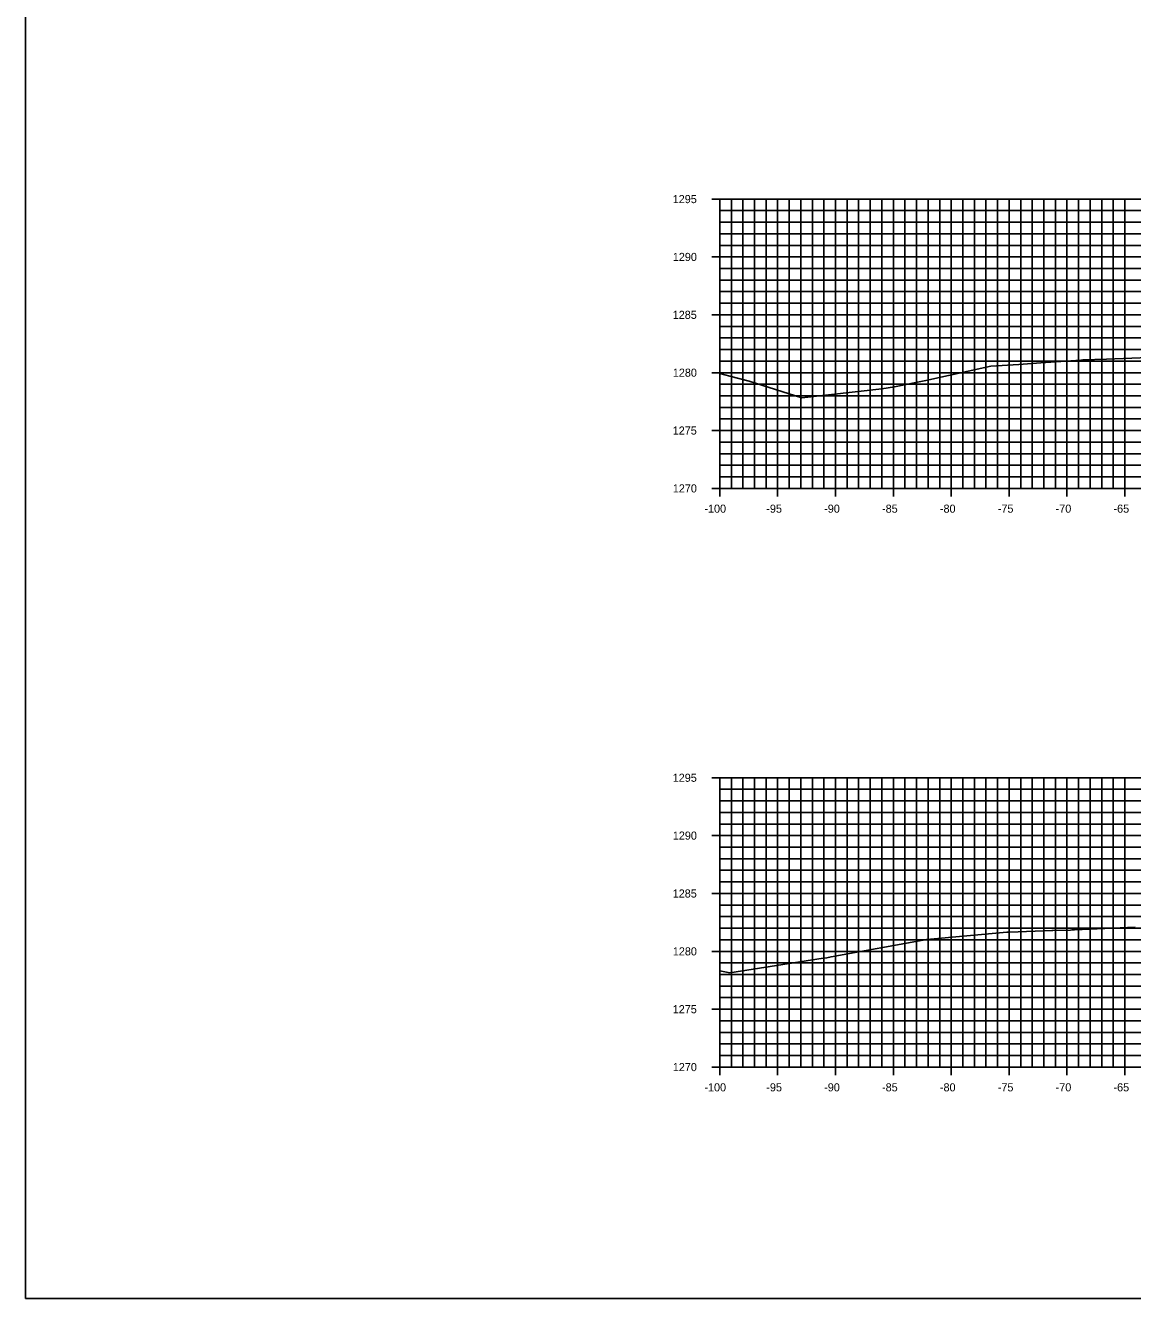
# Model space of a CAD drawing. Extents: x 674939 to 678919, y 750652 to 765176.
# Drawn here: x 678578.5 to 678674.2, y 758972.6 to 759082.6 of the extents above; entities that cross this region are included whole.
import ezdxf

# ---------------------------------------------------------------- set-up
doc = ezdxf.new("R2010")
doc.units = 0
for name, color, linetype in [('Level 10', 7, 'Continuous'), ('Level 20', 7, 'Continuous'), ('Level 4', 7, 'Continuous'), ('Level 8', 7, 'Continuous'), ('Level 9', 7, 'Continuous')]:
    doc.layers.add(name, color=color, linetype=linetype)

msp = doc.modelspace()

# ---------------------------------------------------------------- linework, layer by layer
at = {"layer": 'Level 10'}
for points in [[(678638.53, 759052.49), (678639.41, 759052.24), (678641.08, 759051.82), (678645.63, 759050.37), (678652.53, 759051.16), (678653.62, 759051.32), (678656.33, 759051.86), (678661.96, 759053.1), (678664.37, 759053.27), (678666.28, 759053.41), (678669.72, 759053.64), (678669.9, 759053.66), (678671.95, 759053.73), (678676.31, 759053.88)], [(678638.53, 759000.86), (678639.41, 759000.69), (678647.47, 759001.97), (678647.77, 759002), (678648.14, 759002.09), (678656.42, 759003.58), (678663.32, 759004.2), (678663.44, 759004.21), (678663.59, 759004.22), (678667.23, 759004.36), (678667.3, 759004.36), (678667.31, 759004.36), (678668.84, 759004.39), (678668.94, 759004.4), (678669.17, 759004.41), (678674.42, 759004.64)]]:
    msp.add_lwpolyline(points, dxfattribs=at)
at = {"layer": 'Level 20'}
for p, q in [((678638.53, 759067.55), (678838.53, 759067.55)), ((678638.53, 759042.55), (678638.53, 759067.55)), ((678639.53, 759042.55), (678639.53, 759067.55)), ((678640.53, 759042.55), (678640.53, 759067.55)), ((678641.53, 759042.55), (678641.53, 759067.55)), ((678642.53, 759042.55), (678642.53, 759067.55)), ((678643.53, 759042.55), (678643.53, 759067.55)), ((678644.53, 759042.55), (678644.53, 759067.55)), ((678645.53, 759042.55), (678645.53, 759067.55)), ((678646.53, 759042.55), (678646.53, 759067.55)), ((678647.53, 759042.55), (678647.53, 759067.55)), ((678648.53, 759042.55), (678648.53, 759067.55)), ((678649.53, 759042.55), (678649.53, 759067.55)), ((678650.53, 759042.55), (678650.53, 759067.55)), ((678651.53, 759042.55), (678651.53, 759067.55)), ((678652.53, 759042.55), (678652.53, 759067.55)), ((678653.53, 759042.55), (678653.53, 759067.55)), ((678654.53, 759042.55), (678654.53, 759067.55)), ((678655.53, 759042.55), (678655.53, 759067.55)), ((678656.53, 759042.55), (678656.53, 759067.55)), ((678657.53, 759042.55), (678657.53, 759067.55)), ((678658.53, 759042.55), (678658.53, 759067.55)), ((678659.53, 759042.55), (678659.53, 759067.55)), ((678660.53, 759042.55), (678660.53, 759067.55)), ((678661.53, 759042.55), (678661.53, 759067.55)), ((678662.53, 759042.55), (678662.53, 759067.55)), ((678663.53, 759042.55), (678663.53, 759067.55)), ((678664.53, 759042.55), (678664.53, 759067.55)), ((678665.53, 759042.55), (678665.53, 759067.55)), ((678666.53, 759042.55), (678666.53, 759067.55)), ((678667.53, 759042.55), (678667.53, 759067.55)), ((678668.53, 759042.55), (678668.53, 759067.55)), ((678669.53, 759042.55), (678669.53, 759067.55)), ((678670.53, 759042.55), (678670.53, 759067.55)), ((678671.53, 759042.55), (678671.53, 759067.55)), ((678672.53, 759042.55), (678672.53, 759067.55)), ((678673.53, 759042.55), (678673.53, 759067.55)), ((678638.53, 759066.55), (678838.53, 759066.55)), ((678638.53, 759065.55), (678838.53, 759065.55)), ((678638.53, 759064.55), (678838.53, 759064.55)), ((678638.53, 759063.55), (678838.53, 759063.55)), ((678638.53, 759062.55), (678838.53, 759062.55)), ((678638.53, 759061.55), (678838.53, 759061.55)), ((678638.53, 759060.55), (678838.53, 759060.55)), ((678638.53, 759059.55), (678838.53, 759059.55)), ((678638.53, 759058.55), (678838.53, 759058.55)), ((678638.53, 759057.55), (678838.53, 759057.55)), ((678638.53, 759056.55), (678838.53, 759056.55)), ((678638.53, 759055.55), (678838.53, 759055.55)), ((678638.53, 759054.55), (678838.53, 759054.55)), ((678638.53, 759053.55), (678838.53, 759053.55)), ((678638.53, 759052.55), (678838.53, 759052.55)), ((678638.53, 759051.55), (678838.53, 759051.55)), ((678638.53, 759050.55), (678838.53, 759050.55)), ((678638.53, 759049.55), (678838.53, 759049.55)), ((678638.53, 759048.55), (678838.53, 759048.55)), ((678638.53, 759047.55), (678838.53, 759047.55)), ((678638.53, 759046.55), (678838.53, 759046.55)), ((678638.53, 759045.55), (678838.53, 759045.55)), ((678638.53, 759044.55), (678838.53, 759044.55)), ((678638.53, 759043.55), (678838.53, 759043.55)), ((678638.53, 759042.55), (678838.53, 759042.55)), ((678638.53, 759017.55), (678838.53, 759017.55)), ((678638.53, 758992.55), (678638.53, 759017.55)), ((678638.53, 759016.55), (678838.53, 759016.55)), ((678639.53, 758992.55), (678639.53, 759017.55)), ((678640.53, 758992.55), (678640.53, 759017.55)), ((678641.53, 758992.55), (678641.53, 759017.55)), ((678642.53, 758992.55), (678642.53, 759017.55)), ((678643.53, 758992.55), (678643.53, 759017.55)), ((678644.53, 758992.55), (678644.53, 759017.55)), ((678645.53, 758992.55), (678645.53, 759017.55)), ((678646.53, 758992.55), (678646.53, 759017.55)), ((678647.53, 758992.55), (678647.53, 759017.55)), ((678648.53, 758992.55), (678648.53, 759017.55)), ((678649.53, 758992.55), (678649.53, 759017.55)), ((678650.53, 758992.55), (678650.53, 759017.55)), ((678651.53, 758992.55), (678651.53, 759017.55)), ((678652.53, 758992.55), (678652.53, 759017.55)), ((678653.53, 758992.55), (678653.53, 759017.55)), ((678654.53, 758992.55), (678654.53, 759017.55)), ((678655.53, 758992.55), (678655.53, 759017.55)), ((678656.53, 758992.55), (678656.53, 759017.55)), ((678657.53, 758992.55), (678657.53, 759017.55)), ((678658.53, 758992.55), (678658.53, 759017.55)), ((678659.53, 758992.55), (678659.53, 759017.55)), ((678660.53, 758992.55), (678660.53, 759017.55)), ((678661.53, 758992.55), (678661.53, 759017.55)), ((678662.53, 758992.55), (678662.53, 759017.55)), ((678663.53, 758992.55), (678663.53, 759017.55)), ((678664.53, 758992.55), (678664.53, 759017.55)), ((678665.53, 758992.55), (678665.53, 759017.55)), ((678666.53, 758992.55), (678666.53, 759017.55)), ((678667.53, 758992.55), (678667.53, 759017.55)), ((678668.53, 758992.55), (678668.53, 759017.55)), ((678669.53, 758992.55), (678669.53, 759017.55)), ((678670.53, 758992.55), (678670.53, 759017.55)), ((678671.53, 758992.55), (678671.53, 759017.55)), ((678672.53, 758992.55), (678672.53, 759017.55)), ((678673.53, 758992.55), (678673.53, 759017.55)), ((678638.53, 759015.55), (678838.53, 759015.55)), ((678638.53, 759014.55), (678838.53, 759014.55)), ((678638.53, 759013.55), (678838.53, 759013.55)), ((678638.53, 759012.55), (678838.53, 759012.55)), ((678638.53, 759011.55), (678838.53, 759011.55)), ((678638.53, 759010.55), (678838.53, 759010.55)), ((678638.53, 759009.55), (678838.53, 759009.55)), ((678638.53, 759008.55), (678838.53, 759008.55)), ((678638.53, 759007.55), (678838.53, 759007.55)), ((678638.53, 759006.55), (678838.53, 759006.55)), ((678638.53, 759005.55), (678838.53, 759005.55)), ((678638.53, 759004.55), (678838.53, 759004.55)), ((678638.53, 759003.55), (678838.53, 759003.55)), ((678638.53, 759002.55), (678838.53, 759002.55)), ((678638.53, 759001.55), (678838.53, 759001.55)), ((678638.53, 759000.55), (678838.53, 759000.55)), ((678638.53, 758999.55), (678838.53, 758999.55)), ((678638.53, 758998.55), (678838.53, 758998.55)), ((678638.53, 758997.55), (678838.53, 758997.55)), ((678638.53, 758996.55), (678838.53, 758996.55)), ((678638.53, 758995.55), (678838.53, 758995.55)), ((678638.53, 758994.55), (678838.53, 758994.55)), ((678638.53, 758993.55), (678838.53, 758993.55)), ((678638.53, 758992.55), (678838.53, 758992.55))]:
    msp.add_line(p, q, dxfattribs=at)
at = {"layer": 'Level 4'}
msp.add_lwpolyline([(678578.53, 758972.55), (678918.53, 758972.55), (678918.53, 759192.55), (678578.53, 759192.55)], close=True, dxfattribs=at)
at = {"layer": 'Level 8'}
for p, q in [((678637.83, 759067.55), (678639.23, 759067.55)), ((678638.53, 759042.55), (678638.53, 759067.55)), ((678638.53, 759066.55), (678638.88, 759066.55)), ((678638.53, 759065.55), (678638.88, 759065.55)), ((678638.53, 759064.55), (678638.88, 759064.55)), ((678638.53, 759063.55), (678638.88, 759063.55)), ((678637.83, 759062.55), (678639.23, 759062.55)), ((678638.53, 759061.55), (678638.88, 759061.55)), ((678638.53, 759060.55), (678638.88, 759060.55)), ((678638.53, 759059.55), (678638.88, 759059.55)), ((678638.53, 759058.55), (678638.88, 759058.55)), ((678637.83, 759057.55), (678639.23, 759057.55)), ((678638.53, 759056.55), (678638.88, 759056.55)), ((678638.53, 759055.55), (678638.88, 759055.55)), ((678638.53, 759054.55), (678638.88, 759054.55)), ((678638.53, 759053.55), (678638.88, 759053.55)), ((678637.83, 759052.55), (678639.23, 759052.55)), ((678638.53, 759051.55), (678638.88, 759051.55)), ((678638.53, 759050.55), (678638.88, 759050.55)), ((678638.53, 759049.55), (678638.88, 759049.55)), ((678638.53, 759048.55), (678638.88, 759048.55)), ((678637.83, 759047.55), (678639.23, 759047.55)), ((678638.53, 759046.55), (678638.88, 759046.55)), ((678638.53, 759045.55), (678638.88, 759045.55)), ((678638.53, 759044.55), (678638.88, 759044.55)), ((678638.53, 759043.55), (678638.88, 759043.55)), ((678638.53, 759041.85), (678638.53, 759043.25)), ((678643.53, 759041.85), (678643.53, 759043.25)), ((678648.53, 759041.85), (678648.53, 759043.25)), ((678653.53, 759041.85), (678653.53, 759043.25)), ((678658.53, 759041.85), (678658.53, 759043.25)), ((678663.53, 759041.85), (678663.53, 759043.25)), ((678668.53, 759041.85), (678668.53, 759043.25)), ((678673.53, 759041.85), (678673.53, 759043.25)), ((678637.83, 759042.55), (678639.23, 759042.55)), ((678638.53, 759042.55), (678838.53, 759042.55)), ((678637.83, 759017.55), (678639.23, 759017.55)), ((678638.53, 758992.55), (678638.53, 759017.55)), ((678638.53, 759016.55), (678638.88, 759016.55)), ((678638.53, 759015.55), (678638.88, 759015.55)), ((678638.53, 759014.55), (678638.88, 759014.55)), ((678638.53, 759013.55), (678638.88, 759013.55)), ((678637.83, 759012.55), (678639.23, 759012.55)), ((678638.53, 759011.55), (678638.88, 759011.55)), ((678638.53, 759010.55), (678638.88, 759010.55)), ((678638.53, 759009.55), (678638.88, 759009.55)), ((678638.53, 759008.55), (678638.88, 759008.55)), ((678637.83, 759007.55), (678639.23, 759007.55)), ((678638.53, 759006.55), (678638.88, 759006.55)), ((678638.53, 759005.55), (678638.88, 759005.55)), ((678638.53, 759004.55), (678638.88, 759004.55)), ((678638.53, 759003.55), (678638.88, 759003.55)), ((678637.83, 759002.55), (678639.23, 759002.55)), ((678638.53, 759001.55), (678638.88, 759001.55)), ((678638.53, 759000.55), (678638.88, 759000.55)), ((678638.53, 758999.55), (678638.88, 758999.55)), ((678638.53, 758998.55), (678638.88, 758998.55)), ((678637.83, 758997.55), (678639.23, 758997.55)), ((678638.53, 758996.55), (678638.88, 758996.55)), ((678638.53, 758995.55), (678638.88, 758995.55)), ((678638.53, 758994.55), (678638.88, 758994.55)), ((678638.53, 758993.55), (678638.88, 758993.55)), ((678637.83, 758992.55), (678639.23, 758992.55)), ((678638.53, 758991.85), (678638.53, 758993.25)), ((678638.53, 758992.55), (678838.53, 758992.55)), ((678643.53, 758991.85), (678643.53, 758993.25)), ((678648.53, 758991.85), (678648.53, 758993.25)), ((678653.53, 758991.85), (678653.53, 758993.25)), ((678658.53, 758991.85), (678658.53, 758993.25)), ((678663.53, 758991.85), (678663.53, 758993.25)), ((678668.53, 758991.85), (678668.53, 758993.25)), ((678673.53, 758991.85), (678673.53, 758993.25))]:
    msp.add_line(p, q, dxfattribs=at)

# ---------------------------------------------------------------- texts
at = {"layer": 'Level 9'}
for s, p in [('1295', (678634.46, 759067.2)), ('1290', (678634.47, 759062.2)), ('1285', (678634.46, 759057.2)), ('1280', (678634.47, 759052.2)), ('1275', (678634.46, 759047.2)), ('1270', (678634.47, 759042.2)), ('-100', (678637.2, 759040.45)), ('-95', (678642.55, 759040.45)), ('-90', (678647.55, 759040.45)), ('-85', (678652.55, 759040.45)), ('-80', (678657.55, 759040.45)), ('-75', (678662.55, 759040.45)), ('-70', (678667.55, 759040.45)), ('-65', (678672.55, 759040.45)), ('1295', (678634.46, 759017.2)), ('1290', (678634.47, 759012.2)), ('1285', (678634.46, 759007.2)), ('1280', (678634.47, 759002.2)), ('1275', (678634.46, 758997.2)), ('1270', (678634.47, 758992.2)), ('-100', (678637.2, 758990.45)), ('-95', (678642.55, 758990.45)), ('-90', (678647.55, 758990.45)), ('-85', (678652.55, 758990.45)), ('-80', (678657.55, 758990.45)), ('-75', (678662.55, 758990.45)), ('-70', (678667.55, 758990.45)), ('-65', (678672.55, 758990.45))]:
    msp.add_text(s, height=0.7, dxfattribs=at).set_placement(p)

doc.saveas('drawing.dxf')
